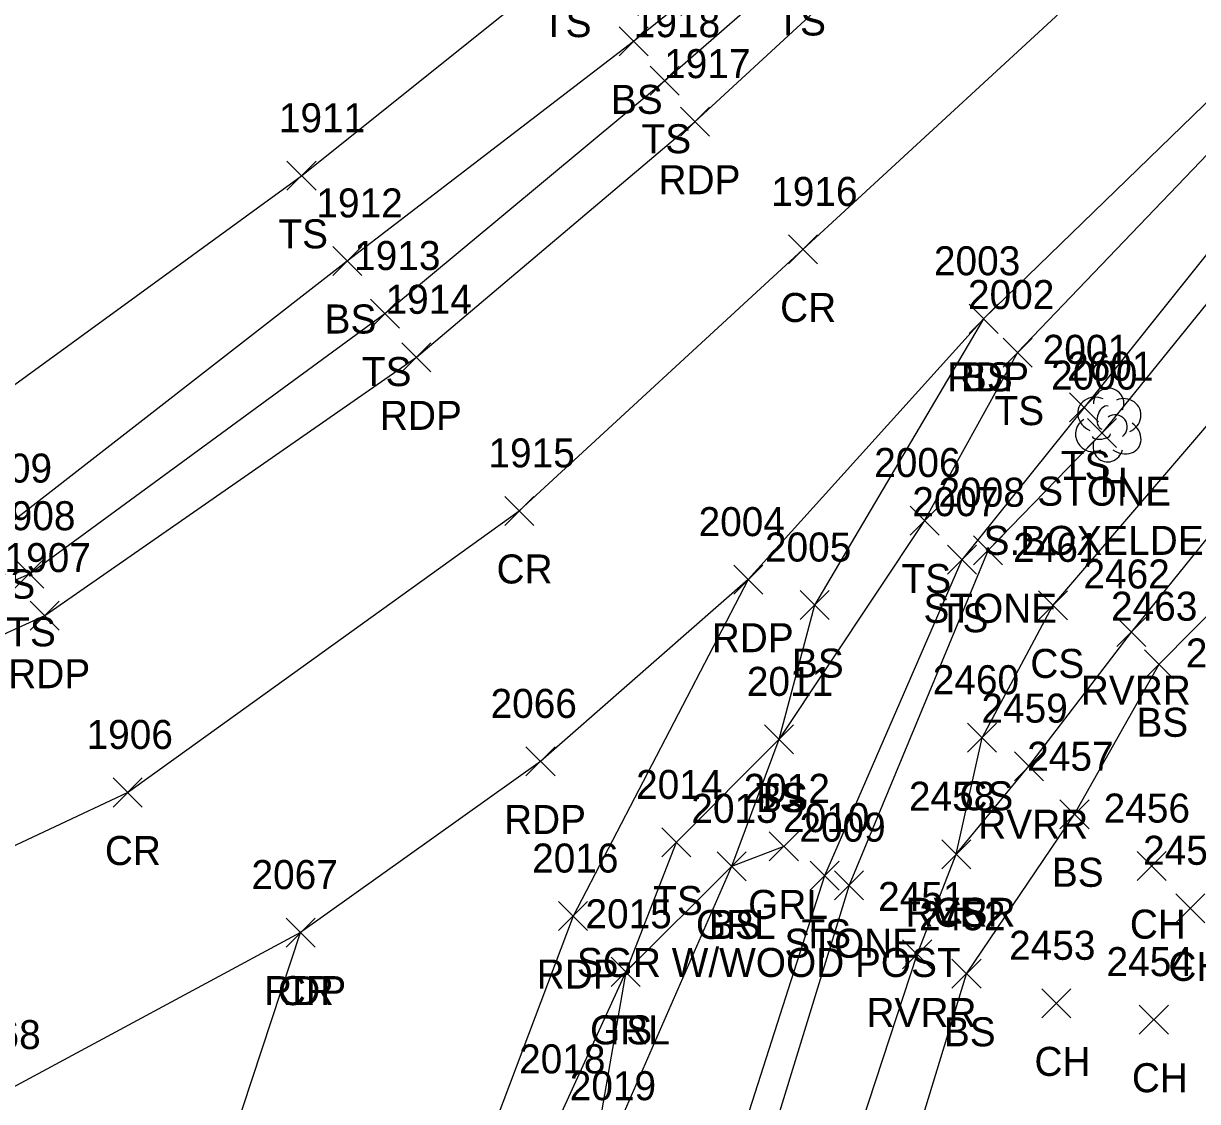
# Model space of a CAD drawing. Extents: x 1459992 to 1461532, y 647785 to 648535.
# Drawn here: x 1461256.6 to 1461337.5, y 648282.2 to 648356.5 of the extents above; entities that cross this region are included whole.
import ezdxf

# ---------------------------------------------------------------- set-up
doc = ezdxf.new("R2010")
doc.units = 0
for name, color, linetype in [('L_A', 7, 'Continuous'), ('L_C', 7, 'Continuous'), ('L_I', 7, 'Continuous'), ('L_TIC', 7, 'Continuous'), ('LASF', 7, 'Continuous'), ('LAWE', 7, 'Continuous'), ('LELB', 7, 'Continuous'), ('LTD', 7, 'Continuous'), ('P_A', 7, 'Continuous'), ('P_I', 7, 'Continuous'), ('P_TIC', 7, 'Continuous'), ('PET', 7, 'Continuous'), ('PRC', 7, 'Continuous'), ('R_A', 7, 'Continuous'), ('R_C', 7, 'Continuous'), ('R_I', 7, 'Continuous'), ('R_TIC', 7, 'Continuous'), ('RGR', 7, 'Continuous')]:
    doc.layers.add(name, color=color, linetype=linetype)

msp = doc.modelspace()

# ---------------------------------------------------------------- linework, layer by layer
at = {"layer": 'L_TIC'}
for points in [[(1461297.642, 648354.282), (1461299.642, 648356.282)], [(1461299.642, 648354.282), (1461297.642, 648356.282)], [(1461299.786, 648351.568), (1461301.786, 648353.568)], [(1461301.786, 648351.568), (1461299.786, 648353.568)], [(1461274.763, 648345.015), (1461276.763, 648347.015)], [(1461276.763, 648345.015), (1461274.763, 648347.015)], [(1461277.915, 648339.145), (1461279.915, 648341.145)], [(1461279.915, 648339.145), (1461277.915, 648341.145)], [(1461280.514, 648335.52), (1461282.514, 648337.52)], [(1461282.514, 648335.52), (1461280.514, 648337.52)], [(1461321.757, 648335.157), (1461323.757, 648337.157)], [(1461323.757, 648335.157), (1461321.757, 648337.157)], [(1461324.103, 648332.829), (1461326.103, 648334.829)], [(1461326.103, 648332.829), (1461324.103, 648334.829)], [(1461328.681, 648329.054), (1461330.681, 648331.054)], [(1461330.681, 648329.054), (1461328.681, 648331.054)], [(1461329.912, 648327.279), (1461331.912, 648329.279)], [(1461331.912, 648327.279), (1461329.912, 648329.279)], [(1461317.696, 648321.255), (1461319.696, 648323.255)], [(1461319.696, 648321.255), (1461317.696, 648323.255)], [(1461322.073, 648319.206), (1461324.073, 648321.206)], [(1461324.073, 648319.206), (1461322.073, 648321.206)], [(1461320.263, 648318.556), (1461322.263, 648320.556)], [(1461322.263, 648318.556), (1461320.263, 648320.556)], [(1461256.012, 648317.586), (1461258.012, 648319.586)], [(1461258.012, 648317.586), (1461256.012, 648319.586)], [(1461310.114, 648315.428), (1461312.114, 648317.428)], [(1461312.114, 648315.428), (1461310.114, 648317.428)], [(1461326.539, 648315.406), (1461328.539, 648317.406)], [(1461328.539, 648315.406), (1461326.539, 648317.406)], [(1461326.539, 648315.406), (1461328.539, 648317.406)], [(1461328.539, 648315.406), (1461326.539, 648317.406)], [(1461331.947, 648313.572), (1461333.947, 648315.572)], [(1461333.947, 648313.572), (1461331.947, 648315.572)], [(1461333.847, 648311.35), (1461335.847, 648313.35)], [(1461335.847, 648311.35), (1461333.847, 648313.35)], [(1461307.654, 648306.17), (1461309.654, 648308.17)], [(1461309.654, 648306.17), (1461307.654, 648308.17)], [(1461307.654, 648306.17), (1461309.654, 648308.17)], [(1461309.654, 648306.17), (1461307.654, 648308.17)], [(1461321.651, 648306.284), (1461323.651, 648308.284)], [(1461323.651, 648306.284), (1461321.651, 648308.284)], [(1461324.88, 648304.325), (1461326.88, 648306.325)], [(1461326.88, 648304.325), (1461324.88, 648306.325)], [(1461328.024, 648301.011), (1461330.024, 648303.011)], [(1461330.024, 648301.011), (1461328.024, 648303.011)], [(1461300.589, 648299.067), (1461302.589, 648301.067)], [(1461302.589, 648299.067), (1461300.589, 648301.067)], [(1461319.876, 648298.253), (1461321.876, 648300.253)], [(1461321.876, 648298.253), (1461319.876, 648300.253)], [(1461319.876, 648298.253), (1461321.876, 648300.253)], [(1461321.876, 648298.253), (1461319.876, 648300.253)], [(1461304.395, 648297.419), (1461306.395, 648299.419)], [(1461306.395, 648297.419), (1461304.395, 648299.419)], [(1461333.349, 648297.438), (1461335.349, 648299.438)], [(1461335.349, 648297.438), (1461333.349, 648299.438)], [(1461310.802, 648296.779), (1461312.802, 648298.779)], [(1461312.802, 648296.779), (1461310.802, 648298.779)], [(1461312.493, 648296.123), (1461314.493, 648298.123)], [(1461314.493, 648296.123), (1461312.493, 648298.123)], [(1461336.008, 648294.528), (1461338.008, 648296.528)], [(1461338.008, 648294.528), (1461336.008, 648296.528)], [(1461317.184, 648291.347), (1461319.184, 648293.347)], [(1461319.184, 648291.347), (1461317.184, 648293.347)], [(1461297.1, 648290.151), (1461299.1, 648292.151)], [(1461299.1, 648290.151), (1461297.1, 648292.151)], [(1461320.583, 648290.019), (1461322.583, 648292.019)], [(1461322.583, 648290.019), (1461320.583, 648292.019)], [(1461326.776, 648287.98), (1461328.776, 648289.98)], [(1461328.776, 648287.98), (1461326.776, 648289.98)], [(1461333.49, 648286.854), (1461335.49, 648288.854)], [(1461335.49, 648286.854), (1461333.49, 648288.854)]]:
    msp.add_lwpolyline(points, dxfattribs=at)
at = {"layer": 'LASF'}
msp.add_lwpolyline([(1461385.213, 648380.492), (1461366.248, 648363.55), (1461348.098, 648349.519), (1461330.912, 648328.279), (1461323.073, 648320.206), (1461313.493, 648297.123), (1461306.874, 648275.606), (1461301.288, 648261.14), (1461300.891, 648254.869), (1461298.603, 648250.96), (1461295.289, 648245.182), (1461300.607, 648235.351), (1461302.655, 648226.754), (1461299.855, 648225.177), (1461298.501, 648223.598), (1461297.241, 648222.361)], dxfattribs=at)
at = {"layer": 'LAWE'}
msp.add_lwpolyline([(1461302.494, 648251.414), (1461304.732, 648255.86), (1461311.515, 648272.047), (1461318.184, 648292.347), (1461320.876, 648299.253), (1461325.88, 648305.325), (1461332.947, 648314.572), (1461346.563, 648331.413), (1461356.783, 648344.505), (1461369.936, 648357.821), (1461389.241, 648367.573), (1461411.269, 648373.546), (1461437.484, 648371.916), (1461454.448, 648377.931), (1461478.943, 648382.173)], dxfattribs=at)
at = {"layer": 'LELB'}
for points in [[(1461053.3, 648342.88), (1461057.098, 648347.56), (1461103.595, 648329.253), (1461132.087, 648319.282), (1461156.262, 648311.826), (1461179.796, 648313.289), (1461203.147, 648318.774), (1461223.056, 648334.412), (1461252.962, 648329.421), (1461275.763, 648346.015), (1461293.92, 648360.572), (1461297.896, 648376.517), (1461309.924, 648382.324), (1461323.278, 648384.139), (1461344.646, 648406.601), (1461362.09, 648421.035), (1461389.724, 648443.023), (1461411.957, 648455.767)], [(1461045.753, 648345.161), (1461053.3, 648342.88), (1461099.566, 648323.296), (1461128.931, 648312.136), (1461154.022, 648304.183), (1461179.986, 648301.365), (1461204.478, 648303.002), (1461231.373, 648312.489), (1461255.408, 648321.869), (1461278.915, 648340.145), (1461298.642, 648355.282), (1461307.841, 648362.706), (1461328.637, 648380.088), (1461350.686, 648401.056), (1461366.774, 648414.154), (1461392.597, 648435.989), (1461415.7, 648449.599)], [(1460952.337, 648377.125), (1460985.686, 648362.661), (1461027.426, 648346.632), (1461054.395, 648335.277), (1461097.577, 648319.811), (1461127.298, 648308.177), (1461153.512, 648301.328), (1461179.781, 648297.833), (1461204.836, 648300.473), (1461233.155, 648308.094), (1461257.012, 648318.586), (1461281.514, 648336.52), (1461300.786, 648352.568), (1461310.073, 648360.684), (1461331.77, 648379.204), (1461352.474, 648399.375), (1461367.349, 648413.211), (1461394.437, 648433.888), (1461417.381, 648445.804)], [(1461437.888, 648410.488), (1461418.935, 648407.67), (1461409.615, 648403.832), (1461397.123, 648398.784), (1461381.61, 648386.31), (1461361.675, 648369.148), (1461343.966, 648353.542), (1461325.103, 648333.829), (1461318.696, 648322.255), (1461308.654, 648307.17), (1461301.589, 648300.067), (1461298.1, 648291.151), (1461293.267, 648263.285), (1461293.552, 648252.72), (1461292.905, 648243.507), (1461295.985, 648233.828), (1461296.733, 648225.477), (1461296.732, 648222.487)], [(1461327.539, 648316.406), (1461343.1, 648334.566), (1461354.424, 648346.152), (1461368.865, 648358.513), (1461384.187, 648376.106), (1461404.449, 648390.112), (1461421.156, 648401.485), (1461440.471, 648405.654), (1461476.934, 648404.698)], [(1461409.615, 648403.832), (1461399.481, 648396.087), (1461384.513, 648382.595), (1461363.674, 648367.201), (1461346.459, 648351.009), (1461329.681, 648330.054), (1461321.263, 648319.556), (1461311.802, 648297.779), (1461304.882, 648276.195), (1461298.284, 648261.218), (1461298.603, 648250.96)], [(1461308.559, 648239.319), (1461311.248, 648242.529), (1461308.112, 648247.085), (1461308.77, 648252.863), (1461315.171, 648270.035), (1461321.583, 648291.019), (1461329.024, 648302.011), (1461334.847, 648312.35), (1461349.259, 648326.907), (1461358.54, 648342.564), (1461371.773, 648355.493), (1461390.676, 648365.061), (1461413.445, 648369.696), (1461437.721, 648367.905), (1461455.543, 648374.902), (1461479.25, 648378.908)], [(1461322.757, 648336.157), (1461311.114, 648316.428), (1461308.654, 648307.17), (1461305.395, 648298.419), (1461297.024, 648279.303), (1461298.284, 648261.218)], [(1461320.876, 648299.253), (1461322.651, 648307.284), (1461327.539, 648316.406)]]:
    msp.add_lwpolyline(points, dxfattribs=at)
at = {"layer": 'LTD'}
msp.add_line((1461331.333, 648328.888), (1461331.333, 648328.888), dxfattribs=at)
msp.add_line((1461331.333, 648328.888), (1461331.333, 648328.888), dxfattribs=at)
msp.add_arc((1461331.38, 648330.322), 1.047, 335.52715, 180.95627, dxfattribs=at)
for centre, major_axis, ratio, start_param, end_param in [((1461330.542, 648329.554), (1.21, -0.512), 0.895232, 1.570796, 4.712389), ((1461332.375, 648329.471), (-1.141, -0.483), 0.949671, 1.570796, 4.712389), ((1461331.125, 648329.346), (-0.208, -0.792), 0.645439, 3.141593, 6.283185), ((1461330.25, 648328.179), (0.584, -1.042), 0.959034, 3.141593, 6.283185), ((1461331.833, 648328.721), (-0.5, 0.667), 0.989748, 3.141593, 6.283185), ((1461332.333, 648328.055), (-1.09, 0.792), 0.841452, 1.570796, 4.712389), ((1461331.334, 648327.388), (0.265, 1.061), 0.942809, 1.570796, 4.712389), ((1461330.875, 648328.138), (-0.625, -0.083), 0.423636, 0, 3.141593)]:
    msp.add_ellipse(centre, major_axis=major_axis, ratio=ratio, start_param=start_param, end_param=end_param, dxfattribs=at)
at = {"layer": 'P_TIC'}
for points in [[(1461301.875, 648348.745), (1461303.875, 648350.745)], [(1461303.875, 648348.745), (1461301.875, 648350.745)], [(1461309.308, 648339.937), (1461311.308, 648341.937)], [(1461311.308, 648339.937), (1461309.308, 648341.937)], [(1461321.757, 648335.157), (1461323.757, 648337.157)], [(1461323.757, 648335.157), (1461321.757, 648337.157)], [(1461282.68, 648332.504), (1461284.68, 648334.504)], [(1461284.68, 648332.504), (1461282.68, 648334.504)], [(1461289.771, 648321.917), (1461291.771, 648323.917)], [(1461291.771, 648321.917), (1461289.771, 648323.917)], [(1461305.541, 648317.18), (1461307.541, 648319.18)], [(1461307.541, 648317.18), (1461305.541, 648319.18)], [(1461305.541, 648317.18), (1461307.541, 648319.18)], [(1461307.541, 648317.18), (1461305.541, 648319.18)], [(1461257.072, 648314.7), (1461259.072, 648316.7)], [(1461259.072, 648314.7), (1461257.072, 648316.7)], [(1461291.231, 648304.652), (1461293.231, 648306.652)], [(1461293.231, 648304.652), (1461291.231, 648306.652)], [(1461262.782, 648302.511), (1461264.782, 648304.511)], [(1461264.782, 648302.511), (1461262.782, 648304.511)], [(1461293.48, 648293.993), (1461295.48, 648295.993)], [(1461295.48, 648293.993), (1461293.48, 648295.993)], [(1461274.705, 648292.856), (1461276.705, 648294.856)], [(1461276.705, 648292.856), (1461274.705, 648294.856)], [(1461274.705, 648292.856), (1461276.705, 648294.856)], [(1461276.705, 648292.856), (1461274.705, 648294.856)]]:
    msp.add_lwpolyline(points, dxfattribs=at)
at = {"layer": 'PET'}
for points in [[(1460950.925, 648374.58), (1460984.688, 648360.316), (1461025.416, 648343.732), (1461053.377, 648332.515), (1461095.054, 648316.172), (1461126.173, 648304.953), (1461152.616, 648298.479), (1461179.858, 648295.542), (1461205.349, 648297.276), (1461234.43, 648304.944), (1461258.072, 648315.7), (1461283.68, 648333.504), (1461302.875, 648349.745), (1461333.022, 648377.548), (1461355.022, 648397.126), (1461371.06, 648410.569), (1461396.623, 648429.432), (1461418.974, 648443.378)], [(1461431.711, 648423.556), (1461406.606, 648408.469), (1461395.323, 648400.735), (1461379.715, 648387.972), (1461359.995, 648370.892), (1461342.503, 648355.317), (1461322.757, 648336.157), (1461306.541, 648318.18), (1461292.231, 648305.652), (1461275.705, 648293.856), (1461255.229, 648282.826), (1461238.596, 648275.701), (1461226.2, 648272.493), (1461213.087, 648269.852), (1461197.04, 648267.634), (1461176.943, 648267.356), (1461164.213, 648269.583)], [(1461306.541, 648318.18), (1461294.48, 648294.993), (1461287.028, 648275.217), (1461283.474, 648264.713), (1461281.187, 648252.679), (1461282.653, 648241.085), (1461286.238, 648232.059), (1461291.364, 648224.94), (1461295.532, 648221.126), (1461291.541, 648216.46), (1461287.609, 648211.808)]]:
    msp.add_lwpolyline(points, dxfattribs=at)
at = {"layer": 'PRC'}
for points in [[(1460946.831, 648364.552), (1460979.811, 648350.874), (1461020.892, 648333.411), (1461048.045, 648322.3), (1461089.526, 648305.666), (1461120.417, 648294.121), (1461149.174, 648286.001), (1461180.556, 648282.29), (1461207.176, 648283.702), (1461238.838, 648291.787), (1461263.782, 648303.511), (1461290.771, 648322.917), (1461310.308, 648340.937), (1461342.224, 648370.367), (1461365.166, 648390.4), (1461371.568, 648396.042), (1461402.619, 648419.98), (1461424.86, 648433.53)], [(1461291.541, 648216.46), (1461279.758, 648227.625), (1461267.854, 648239.793), (1461268.374, 648256.519), (1461269.056, 648273.722), (1461275.705, 648293.856)]]:
    msp.add_lwpolyline(points, dxfattribs=at)
at = {"layer": 'R_TIC'}
for points in [[(1461307.996, 648298.797), (1461309.996, 648300.797)], [(1461309.996, 648298.797), (1461307.996, 648300.797)], [(1461304.395, 648297.419), (1461306.395, 648299.419)], [(1461306.395, 648297.419), (1461304.395, 648299.419)], [(1461297.1, 648290.151), (1461299.1, 648292.151)], [(1461299.1, 648290.151), (1461297.1, 648292.151)]]:
    msp.add_lwpolyline(points, dxfattribs=at)
at = {"layer": 'RGR'}
msp.add_lwpolyline([(1461308.996, 648299.797), (1461305.395, 648298.419), (1461298.1, 648291.151), (1461293.529, 648281.151), (1461288.214, 648264.827), (1461285.682, 648256.142), (1461285.047, 648246.912), (1461288.678, 648232.012), (1461291.542, 648226.044), (1461295.805, 648221.25)], dxfattribs=at)

# ---------------------------------------------------------------- texts
at = {"layer": 'L_A'}
for s, p in [('TS', (1461292.329, 648355.572)), ('TS', (1461308.483, 648355.684)), ('BS', (1461297.083, 648350.282)), ('TS', (1461299.195, 648347.568)), ('TS', (1461274.173, 648341.015)), ('BS', (1461277.355, 648335.145)), ('TS', (1461279.924, 648331.52)), ('BS', (1461321.198, 648331.157)), ('TS', (1461323.513, 648328.829)), ('TS', (1461328.091, 648325.054)), ('H', (1461330.766, 648323.888)), ('STONE', (1461326.456, 648323.279)), ('BS', (1461253.848, 648316.869)), ('TS', (1461317.106, 648317.255)), ('STONE', (1461318.616, 648315.206)), ('TS', (1461319.673, 648314.556)), ('TS', (1461255.422, 648313.586)), ('BS', (1461309.555, 648311.428)), ('CS', (1461325.98, 648311.406)), ('CS', (1461325.98, 648311.406)), ('RVRR', (1461329.459, 648309.572)), ('BS', (1461333.288, 648307.35)), ('TS', (1461307.063, 648302.17)), ('BS', (1461307.095, 648302.17)), ('CS', (1461321.091, 648302.284)), ('RVRR', (1461322.392, 648300.325)), ('BS', (1461327.465, 648297.011)), ('TS', (1461299.999, 648295.067)), ('RVRR', (1461317.388, 648294.253)), ('CS', (1461319.317, 648294.253)), ('BS', (1461303.836, 648293.419)), ('CH', (1461332.837, 648293.438)), ('TS', (1461310.211, 648292.779)), ('STONE', (1461309.037, 648292.123)), ('CH', (1461335.496, 648290.528)), ('RVRR', (1461314.696, 648287.347)), ('TS', (1461296.51, 648286.151)), ('BS', (1461320.024, 648286.019)), ('CH', (1461326.265, 648283.98)), ('CH', (1461332.978, 648282.854))]:
    msp.add_text(s, height=2, dxfattribs=at).set_placement(p)
at = {"layer": 'L_C'}
msp.add_text('S.BOXELDER', height=2, dxfattribs=at).set_placement((1461322.759, 648319.888))
at = {"layer": 'L_I'}
for s, p in [('1918', (1461298.66, 648355.568)), ('1911', (1461274.204, 648349.015)), ('1912', (1461276.789, 648343.145)), ('1913', (1461279.388, 648339.52)), ('2003', (1461319.339, 648339.157)), ('2002', (1461321.686, 648336.829)), ('2001', (1461326.831, 648333.054)), ('2601', (1461328.514, 648331.888)), ('2000', (1461327.408, 648331.279)), ('1909', (1461252.628, 648324.869)), ('2006', (1461315.224, 648325.255)), ('2008', (1461319.656, 648323.206)), ('2007', (1461317.846, 648322.556)), ('1908', (1461254.241, 648321.586)), ('2005', (1461307.697, 648319.428)), ('2461', (1461324.799, 648319.406)), ('2461', (1461324.799, 648319.406)), ('2462', (1461329.64, 648317.572)), ('2463', (1461331.54, 648315.35)), ('2464', (1461336.696, 648312.127)), ('2011', (1461306.449, 648310.17)), ('2011', (1461306.449, 648310.17)), ('2460', (1461319.257, 648310.284)), ('2459', (1461322.612, 648308.325)), ('2457', (1461325.765, 648305.011)), ('2014', (1461298.818, 648303.067)), ('2458', (1461317.616, 648302.253)), ('2458', (1461317.616, 648302.253)), ('2013', (1461302.623, 648301.419)), ('2456', (1461331.034, 648301.438)), ('2010', (1461308.944, 648300.779)), ('2009', (1461310.068, 648300.123)), ('2455', (1461333.748, 648298.528)), ('2451', (1461315.491, 648295.347)), ('2015', (1461295.329, 648294.151)), ('2452', (1461318.323, 648294.019)), ('2453', (1461324.517, 648291.98)), ('2454', (1461331.23, 648290.854)), ('2019', (1461294.245, 648282.303))]:
    msp.add_text(s, height=2, dxfattribs=at).set_placement(p)
at = {"layer": 'P_A'}
for s, p in [('RDP', (1461300.363, 648344.745)), ('CR', (1461308.741, 648335.937)), ('RDP', (1461320.245, 648331.157)), ('RDP', (1461281.168, 648328.504)), ('CR', (1461289.204, 648317.917)), ('RDP', (1461304.029, 648313.18)), ('RDP', (1461304.029, 648313.18)), ('RDP', (1461255.56, 648310.7)), ('RDP', (1461289.719, 648300.652)), ('CR', (1461262.215, 648298.511)), ('RDP', (1461291.968, 648289.993)), ('RDP', (1461273.193, 648288.856)), ('CR', (1461274.138, 648288.856))]:
    msp.add_text(s, height=2, dxfattribs=at).set_placement(p)
at = {"layer": 'P_I'}
for s, p in [('1917', (1461300.749, 648352.745)), ('1916', (1461308.127, 648343.937)), ('2003', (1461319.339, 648339.157)), ('1914', (1461281.554, 648336.504)), ('1915', (1461288.645, 648325.917)), ('2004', (1461303.124, 648321.18)), ('2004', (1461303.124, 648321.18)), ('1907', (1461255.301, 648318.7)), ('2066', (1461288.79, 648308.652)), ('1906', (1461260.955, 648306.511)), ('2016', (1461291.653, 648297.993)), ('2067', (1461272.319, 648296.856)), ('2067', (1461272.319, 648296.856)), ('2068', (1461251.844, 648285.826))]:
    msp.add_text(s, height=2, dxfattribs=at).set_placement(p)
at = {"layer": 'R_A'}
for p in [(1461306.539, 648294.797), (1461302.938, 648293.419), (1461295.644, 648286.151)]:
    msp.add_text('GRL', height=2, dxfattribs=at).set_placement(p)
at = {"layer": 'R_C'}
msp.add_text('SGR W/WOOD POST', height=2, dxfattribs=at).set_placement((1461294.736, 648290.797))
at = {"layer": 'R_I'}
for s, p in [('2012', (1461306.224, 648302.797)), ('2013', (1461302.623, 648301.419)), ('2015', (1461295.329, 648294.151)), ('2018', (1461290.757, 648284.151))]:
    msp.add_text(s, height=2, dxfattribs=at).set_placement(p)

doc.saveas('drawing.dxf')
